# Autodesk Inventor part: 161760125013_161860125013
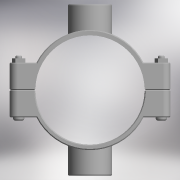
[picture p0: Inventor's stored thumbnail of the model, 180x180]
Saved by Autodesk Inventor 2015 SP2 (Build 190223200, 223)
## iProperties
Created: 2017-05
Part Number: 161760125013_161860125013
Material: Generic
Description: PLASSON DOUBLE SADDLE 125-1.1/4"
Document SubType Name: Modeling
Designer: KIM
Density: 1 g/cm^3
Appearance: Default
Author: KIM
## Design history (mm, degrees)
derived "16176.ipt"
feature "Solid1::16176.ipt"
feature "Solid2::16176.ipt"
tag "TaggingFeature1"
body "Solid1"
body "Solid2"
other parameters: "d0" = 137.5, "d1" = 184, "d2" = 62.5, "d3" = 125, "d4" = 124, "d5" = 0, "d6" = 9.2, "d7" = 184, "d8" = 0.1, "d10" = 0, "d11" = 1.25, "d20" = 1.25, "d23" = 1.25, "d36" = 13, "d37" = 10.4, "d38" = 70.5, "d39" = 0, "d40" = 3, "d41" = 5, "d42" = 0, "d43" = 8, "d44" = 3, "d45" = 0, "d46" = 1.25, "d52" = 38.952, "d53" = 25, "d54" = 0, "d55" = 32, "d57" = 0, "d58" = 135, "d60" = 0, "d62" = 13, "d63" = 10.4, "d66" = 103.2, "d67" = 196, "d68" = 50.6376, "d69" = 38.952, "d70" = 25, "d71" = 0, "d72" = 32, "d74" = 0, "d75" = 1.25, "d_" = 125, "B_" = 32, "G_" = 38.952, "A_" = 98, "L_" = 184, "L_1" = 124, "l_2" = 25
